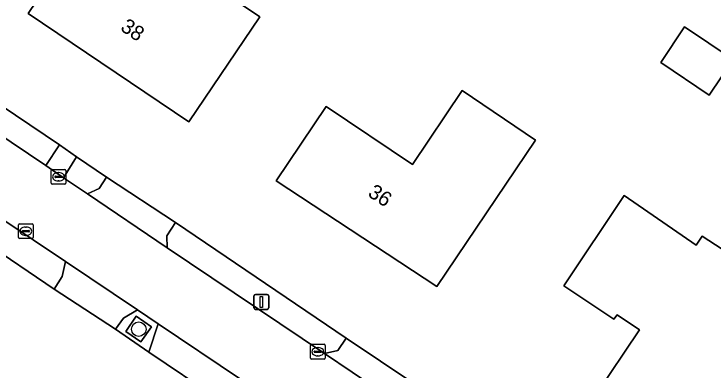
# Model space of a CAD drawing. Extents: x 163266 to 164362, y 381528 to 382286.
# Drawn here: x 164060.23 to 164107.12, y 381691.33 to 381715.24 of the extents above; entities that cross this region are included whole.
import ezdxf

# ---------------------------------------------------------------- set-up
doc = ezdxf.new("R2010")
doc.units = 0
for name, color, linetype in [('IMGEO_Boom', 7, 'Continuous'), ('IMGEO_Erf', 7, 'Continuous'), ('IMGEO_Groenvoorziening', 7, 'Continuous'), ('IMGEO_Haag', 7, 'Continuous'), ('IMGEO_Kolk', 7, 'Continuous'), ('IMGEO_Lichtmast', 7, 'Continuous'), ('IMGEO_Pand', 7, 'Continuous'), ('IMGEO_Pand_nummerreeks', 7, 'Continuous'), ('IMGEO_Rijbaan_lokaal_open', 7, 'Continuous'), ('IMGEO_Voetpad_halfverhard', 7, 'Continuous'), ('IMGEO_Voetpad_open', 7, 'Continuous')]:
    doc.layers.add(name, color=color, linetype=linetype)

msp = doc.modelspace()

# ---------------------------------------------------------------- linework, layer by layer
at = {"layer": 'IMGEO_Boom'}
msp.add_circle((164068.598, 381694.077), 0.489, dxfattribs=at)
at = {"layer": 'IMGEO_Erf'}
for points in [[(164078.899, 381686.041), (164073.867, 381689.437), (164069.267, 381692.537), (164067.04, 381694.07), (164062.928, 381696.773), (164058.221, 381699.932), (164057.006, 381700.767), (164048.821, 381706.271), (164044.279, 381709.335), (164040.497, 381711.904), (164039.261, 381712.764), (164030.048, 381719.001), (164027.004, 381721.09), (164026.19, 381719.875), (164024.486, 381721.003), (164007.31, 381732.546)], [(164031.559, 381727.86), (164063.287, 381706.457), (164064.424, 381705.642), (164066.43, 381704.274), (164071.069, 381701.241), (164082.518, 381693.469), (164087.121, 381690.39), (164089.32, 381688.957), (164093.825, 381685.899), (164104.06, 381678.938), (164146.786, 381709.887), (164146.237, 381710.272), (164149.576, 381715.022), (164151.746, 381713.502), (164150.775, 381712.777), (164154.802, 381715.694), (164148.759, 381719.82), (164152.254, 381724.987)]]:
    msp.add_lwpolyline(points, dxfattribs=at)
for points in [[(164071.963, 381707.997), (164061.188, 381715.267), (164065.935, 381722.342), (164066.184, 381722.181), (164069.555, 381727.14), (164070.796, 381726.319), (164071.099, 381726.754), (164071.974, 381726.143), (164071.602, 381725.61), (164073.778, 381724.158), (164070.475, 381719.251), (164076.716, 381715.038)], [(164105.212, 381714.383), (164108.47, 381712.185), (164106.868, 381709.786), (164103.61, 381711.984)], [(164095.218, 381706.762), (164088.582, 381696.944), (164077.823, 381704.042), (164081.176, 381709.03), (164086.969, 381705.136), (164090.286, 381710.09)], [(164112.396, 381696.416), (164111.657, 381695.307), (164114.302, 381691.708), (164110.774, 381689.099), (164108.5, 381690.568), (164105.182, 381685.587), (164099.203, 381689.608), (164102.186, 381694.039), (164100.68, 381695.046), (164100.475, 381694.738), (164097.114, 381696.979), (164101.164, 381703.044), (164105.978, 381699.718), (164106.398, 381700.327)]]:
    msp.add_lwpolyline(points, close=True, dxfattribs=at)
at = {"layer": 'IMGEO_Groenvoorziening'}
msp.add_lwpolyline([(164069.461, 381694.243), (164068.435, 381694.958), (164067.72, 381693.932), (164068.746, 381693.218)], close=True, dxfattribs=at)
at = {"layer": 'IMGEO_Haag'}
msp.add_lwpolyline([(164069.461, 381694.243), (164068.435, 381694.958), (164067.72, 381693.932), (164068.746, 381693.218)], close=True, dxfattribs=at)
at = {"layer": 'IMGEO_Kolk'}
for p, q in [((164062.715, 381703.879), (164062.715, 381704.731)), ((164062.79, 381704.805), (164063.642, 381704.805)), ((164063.203, 381704.585), (164063.228, 381704.585)), ((164063.716, 381704.731), (164063.716, 381703.879)), ((164062.974, 381704.299), (164062.974, 381704.311)), ((164063.412, 381704.262), (164063.014, 381704.262)), ((164063.017, 381704.348), (164063.415, 381704.348)), ((164063.458, 381704.311), (164063.458, 381704.299)), ((164063.642, 381703.805), (164062.79, 381703.805)), ((164063.226, 381704.025), (164063.201, 381704.025)), ((164060.522, 381700.229), (164060.522, 381701.081)), ((164060.597, 381701.155), (164061.449, 381701.155)), ((164061.01, 381700.935), (164061.035, 381700.935)), ((164061.523, 381701.081), (164061.523, 381700.229)), ((164060.781, 381700.649), (164060.781, 381700.661)), ((164061.219, 381700.612), (164060.821, 381700.612)), ((164060.824, 381700.698), (164061.222, 381700.698)), ((164061.033, 381700.375), (164061.008, 381700.375)), ((164061.265, 381700.661), (164061.265, 381700.649)), ((164061.449, 381700.155), (164060.597, 381700.155)), ((164080.109, 381692.139), (164080.109, 381692.991)), ((164080.184, 381693.065), (164081.036, 381693.065)), ((164080.597, 381692.845), (164080.622, 381692.845)), ((164081.11, 381692.991), (164081.11, 381692.139)), ((164080.368, 381692.559), (164080.368, 381692.571)), ((164080.806, 381692.522), (164080.408, 381692.522)), ((164080.411, 381692.608), (164080.809, 381692.608)), ((164080.852, 381692.571), (164080.852, 381692.559)), ((164081.036, 381692.065), (164080.184, 381692.065)), ((164080.62, 381692.285), (164080.595, 381692.285))]:
    msp.add_line(p, q, dxfattribs=at)
for points in [[(164062.715, 381703.879), (164062.715, 381704.731)], [(164062.79, 381704.805), (164063.642, 381704.805)], [(164063.716, 381704.731), (164063.716, 381703.879)], [(164063.642, 381703.805), (164062.79, 381703.805)], [(164060.522, 381700.229), (164060.522, 381701.081)], [(164060.597, 381701.155), (164061.449, 381701.155)], [(164061.523, 381701.081), (164061.523, 381700.229)], [(164061.449, 381700.155), (164060.597, 381700.155)], [(164080.109, 381692.139), (164080.109, 381692.991)], [(164080.184, 381693.065), (164081.036, 381693.065)], [(164081.11, 381692.991), (164081.11, 381692.139)], [(164081.036, 381692.065), (164080.184, 381692.065)]]:
    msp.add_lwpolyline(points, dxfattribs=at)
for centre, radius, start, end in [((164062.792, 381704.729), 0.0765, 91.552, 178.448), ((164062.792, 381704.729), 0.0765, 91.552, 178.448), ((164063.64, 381704.729), 0.0765, 1.552, 88.448), ((164063.64, 381704.729), 0.0765, 1.552, 88.448), ((164063.014, 381704.308), 0.0403, 85.8775, 175.7526), ((164063.011, 381704.298), 0.0366, 178.938, 274.7102), ((164063.415, 381704.305), 0.043, 264.8664, 352.4533), ((164063.419, 381704.31), 0.0386, 1.7309, 96.639), ((164062.792, 381703.881), 0.0765, 181.552, 268.448), ((164062.792, 381703.881), 0.0765, 181.552, 268.448), ((164063.64, 381703.881), 0.0765, 271.552, 358.448), ((164063.64, 381703.881), 0.0765, 271.552, 358.448), ((164060.599, 381701.079), 0.0765, 91.552, 178.448), ((164060.599, 381701.079), 0.0765, 91.552, 178.448), ((164061.447, 381701.079), 0.0765, 1.552, 88.448), ((164061.447, 381701.079), 0.0765, 1.552, 88.448), ((164060.821, 381700.658), 0.0403, 85.8775, 175.7526), ((164060.818, 381700.648), 0.0366, 178.938, 274.7102), ((164061.222, 381700.655), 0.043, 264.8664, 352.4533), ((164061.226, 381700.66), 0.0386, 1.7309, 96.639), ((164060.599, 381700.231), 0.0765, 181.552, 268.448), ((164060.599, 381700.231), 0.0765, 181.552, 268.448), ((164061.447, 381700.231), 0.0765, 271.552, 358.448), ((164061.447, 381700.231), 0.0765, 271.552, 358.448), ((164080.186, 381692.989), 0.0765, 91.552, 178.448), ((164080.186, 381692.989), 0.0765, 91.552, 178.448), ((164081.034, 381692.989), 0.0765, 1.552, 88.448), ((164081.034, 381692.989), 0.0765, 1.552, 88.448), ((164080.408, 381692.568), 0.0403, 85.8775, 175.7526), ((164080.405, 381692.558), 0.0366, 178.938, 274.7102), ((164080.809, 381692.565), 0.043, 264.8664, 352.4533), ((164080.813, 381692.57), 0.0386, 1.7309, 96.639), ((164080.186, 381692.141), 0.0765, 181.552, 268.448), ((164080.186, 381692.141), 0.0765, 181.552, 268.448), ((164081.034, 381692.141), 0.0765, 271.552, 358.448), ((164081.034, 381692.141), 0.0765, 271.552, 358.448)]:
    msp.add_arc(centre, radius, start, end, dxfattribs=at)
for centre, major_axis, ratio, start_param, end_param in [((164063.202, 381704.305), (-0.387, 0.002), 0.722429, 4.712389, 7.853982), ((164063.227, 381704.305), (-0.39, 0.002), 0.717154, 1.570796, 4.712389), ((164061.009, 381700.655), (-0.387, 0.002), 0.722429, 4.712389, 7.853982), ((164061.034, 381700.655), (-0.39, 0.002), 0.717154, 1.570796, 4.712389), ((164080.596, 381692.565), (-0.387, 0.002), 0.722429, 4.712389, 7.853982), ((164080.621, 381692.565), (-0.39, 0.002), 0.717154, 1.570796, 4.712389)]:
    msp.add_ellipse(centre, major_axis=major_axis, ratio=ratio, start_param=start_param, end_param=end_param, dxfattribs=at)
at = {"layer": 'IMGEO_Lichtmast'}
for p, q in [((164076.323, 381695.506), (164076.323, 381696.306)), ((164076.323, 381696.306), (164076.323, 381695.506)), ((164076.423, 381696.406), (164077.213, 381696.406)), ((164077.213, 381696.406), (164076.423, 381696.406)), ((164077.313, 381696.306), (164077.313, 381695.506)), ((164077.313, 381695.506), (164077.313, 381696.306)), ((164077.213, 381695.406), (164076.423, 381695.406)), ((164076.423, 381695.406), (164077.213, 381695.406))]:
    msp.add_line(p, q, dxfattribs=at)
msp.add_lwpolyline([(164076.743, 381696.281), (164076.893, 381696.281), (164076.893, 381695.531), (164076.743, 381695.531), (164076.743, 381696.281)], dxfattribs=at)
for centre, start, end in [((164076.423, 381696.306), 90, 180), ((164076.423, 381696.306), 90, 180), ((164077.213, 381696.306), 0, 90), ((164077.213, 381696.306), 360, 90), ((164076.423, 381695.506), 180, 270), ((164076.423, 381695.506), 180, 270), ((164077.213, 381695.506), 270, 0), ((164077.213, 381695.506), 270, 0)]:
    msp.add_arc(centre, 0.1, start, end, dxfattribs=at)
at = {"layer": 'IMGEO_Pand'}
for points in [[(164071.963, 381707.997), (164076.716, 381715.038), (164070.475, 381719.251), (164073.778, 381724.158), (164071.602, 381725.61), (164071.974, 381726.143), (164071.099, 381726.754), (164070.796, 381726.319), (164069.555, 381727.14), (164066.184, 381722.181), (164065.935, 381722.342), (164061.188, 381715.267)], [(164103.61, 381711.984), (164106.868, 381709.786), (164108.47, 381712.185), (164105.212, 381714.383)], [(164088.582, 381696.944), (164095.218, 381706.762), (164090.286, 381710.09), (164086.969, 381705.136), (164081.176, 381709.03), (164077.823, 381704.042)], [(164105.182, 381685.587), (164108.5, 381690.568), (164110.774, 381689.099), (164114.302, 381691.708), (164111.657, 381695.307), (164112.396, 381696.416), (164106.398, 381700.327), (164105.978, 381699.718), (164101.164, 381703.044), (164097.114, 381696.979), (164100.475, 381694.738), (164100.68, 381695.046), (164102.186, 381694.039), (164099.203, 381689.608)]]:
    msp.add_lwpolyline(points, close=True, dxfattribs=at)
at = {"layer": 'IMGEO_Rijbaan_lokaal_open'}
for points in [[(163999.252, 381744.71), (164008.883, 381735.535), (164016.853, 381730.156), (164018.052, 381729.344), (164026.521, 381723.615), (164031.695, 381720.116), (164032.207, 381719.769), (164040.374, 381714.295), (164041.569, 381713.485), (164044.956, 381711.196), (164050.355, 381707.539), (164058.116, 381702.356), (164059.338, 381701.54), (164063.682, 381698.622), (164068.515, 381695.376), (164069.911, 381694.44), (164075.422, 381690.725), (164080.018, 381687.656), (164081.239, 381686.855), (164087.153, 381682.87)], [(164087.762, 381678.694), (164083.437, 381672.269), (164089.398, 381668.374), (164102.719, 381677.999), (164093.356, 381684.193), (164087.931, 381687.844), (164086.628, 381688.69), (164081.066, 381692.453), (164070.501, 381699.546), (164065.165, 381703.163), (164063.552, 381704.231), (164062.367, 381705.06), (164032.514, 381725.171), (164030.603, 381726.452), (164030.282, 381726.667)]]:
    msp.add_lwpolyline(points, dxfattribs=at)
at = {"layer": 'IMGEO_Voetpad_halfverhard'}
for points in [[(164032.514, 381725.171), (164062.367, 381705.06), (164063.287, 381706.457), (164031.559, 381727.86), (164030.603, 381726.452)], [(164063.552, 381704.231), (164065.165, 381703.163), (164065.938, 381703.522), (164066.43, 381704.274), (164064.424, 381705.642)], [(164063.682, 381698.622), (164059.338, 381701.54), (164058.221, 381699.932), (164062.928, 381696.773), (164063.47, 381697.624)], [(164081.066, 381692.453), (164081.945, 381692.639), (164082.518, 381693.469), (164071.069, 381701.241), (164070.484, 381700.352), (164070.501, 381699.546)], [(164069.911, 381694.44), (164068.515, 381695.376), (164067.573, 381694.827), (164067.04, 381694.07), (164069.267, 381692.537)], [(164068.746, 381693.218), (164067.72, 381693.932), (164068.435, 381694.958), (164069.461, 381694.243)]]:
    msp.add_lwpolyline(points, close=True, dxfattribs=at)
at = {"layer": 'IMGEO_Voetpad_open'}
for points in [[(164063.552, 381704.231), (164064.424, 381705.642), (164063.287, 381706.457), (164062.367, 381705.06)], [(164066.43, 381704.274), (164065.938, 381703.522), (164065.165, 381703.163), (164070.501, 381699.546), (164070.484, 381700.352), (164071.069, 381701.241)], [(164063.682, 381698.622), (164063.47, 381697.624), (164062.928, 381696.773), (164067.04, 381694.07), (164067.573, 381694.827), (164068.515, 381695.376)], [(164075.422, 381690.725), (164069.911, 381694.44), (164069.267, 381692.537), (164073.867, 381689.437), (164074.423, 381690.291)], [(164086.628, 381688.69), (164086.511, 381689.591), (164087.121, 381690.39), (164082.518, 381693.469), (164081.945, 381692.639), (164081.066, 381692.453)]]:
    msp.add_lwpolyline(points, close=True, dxfattribs=at)

# ---------------------------------------------------------------- texts
at = {"layer": 'IMGEO_Pand_nummerreeks'}
for s, rotation, p in [('38', 325.9889, (164067.305, 381714.18)), ('36', 326.5894, (164083.903, 381703.05))]:
    msp.add_text(s, height=1, rotation=rotation, dxfattribs=at).set_placement(p)

doc.saveas('drawing.dxf')
